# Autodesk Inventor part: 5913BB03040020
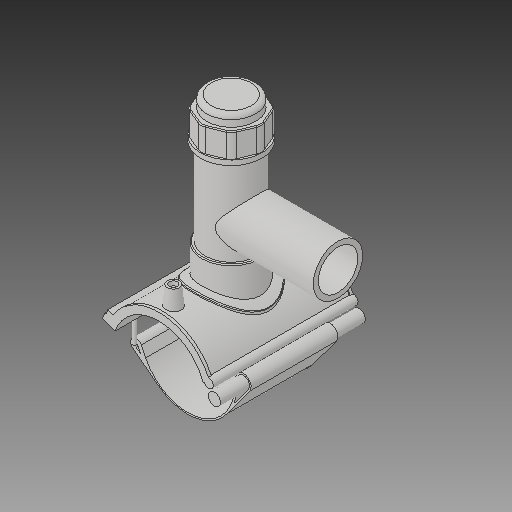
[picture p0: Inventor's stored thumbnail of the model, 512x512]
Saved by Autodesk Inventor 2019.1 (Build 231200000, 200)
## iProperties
Created: 2017-07
Part Number: 5913BB03040020
Material: Generic
Description: PLASSON HIGH VOLUME TAPPING TEE 4''IPSx 2''IPS
Document SubType Name: Modeling
Designer: KIM
Mass: 1712.7 g
Surface Area: 2671.49 cm^2
Volume: 1712.7 cm^3
Density: 1 g/cm^3
Appearance: Default
Author: KIM
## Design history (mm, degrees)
derived "5913B.ipt"
feature "Solid1::5913B.ipt"
feature "Solid2::5913B.ipt"
feature "Solid4::5913B.ipt"
feature "Solid5::5913B.ipt"
tag "TaggingFeature1"
body "Solid1"
body "Solid2"
other parameters: "d0" = 114.1, "d2" = 233.934, "d3" = 28.525, "d4" = 176.022, "d5" = 0, "d6" = 0.1, "d8" = 0, "d40" = 67.63848, "d41" = 91.28, "d43" = 0, "d45" = 0, "d47" = 170.6502, "d78" = 87.05, "d79" = 15, "d80" = 70.4088, "d82" = 5 deg, "d84" = 4, "d85" = 14, "d86" = 0, "d87" = 3, "d88" = 0, "d96" = 132.67548, "d97" = 3.52044, "d98" = 0, "d102" = 1.141, "d120" = 140 deg, "d121" = 24.228, "d122" = 20 deg, "d123" = 325.185, "d124" = 78.0444, "d126" = 0, "d153" = 176.022, "d154" = 0, "d159" = 3.1948, "d162" = 105.6132, "d163" = 0, "d164" = 57.05, "d169" = 4.0905, "d170" = 4.7922, "d172" = 0, "d173" = 1, "d175" = 57.05, "d176" = 20 deg, "d177" = 7.987, "d178" = 15.974, "d180" = 0, "d183" = 6.3896, "d184" = 6.3896, "d187" = 65.037, "d188" = 4.7922, "d189" = 7.987, "d190" = 0, "d191" = 97.5555, "d193" = 4.1076, "d194" = 2.0538, "d195" = 90 deg, "d197" = 0, "d199" = 0, "d200" = 7.987, "d202" = 0, "d203" = 194.818, "d204" = 71.10712, "d205" = 52.39472, "d206" = 63.62216, "d207" = 146.1135, "d208" = 151.95804, "d209" = 181.18074, "d210" = 64.37066, "d211" = 74.8496, "d212" = 59.87968, "d213" = 40.392, "d216" = 0, "d217" = 11.41, "d218" = 5.705, "d219" = 1.141, "d222" = 114.1, "d224" = 0, "d230" = 1.141, "d257" = 131.98, "d258" = 129.794, "d259" = 48.08, "d260" = 60.1, "d263" = 155.956, "d265" = 0, "d267" = 13.00006, "d268" = 2.60001, "d269" = 2.60001, "d271" = 2.60001, "d273" = 0, "d274" = 23.56194, "d275" = 91.28, "d277" = 45.64, "d278" = 182.56, "d280" = 0, "d281" = 114.1, "d283" = 0, "d285" = 0, "d290" = 11.41, "d291" = 14.833, "d293" = 62.755, "d294" = 58.7615, "d296" = 17.115, "d297" = 13.692, "d_" = 114.1, "B_" = 155.956, "L_" = 176.022, "d_t" = 6, "H_2" = 194.818, "H_1" = 74.93, "d_1" = 60.1, "H_" = 129.794, "d1" = 130.074, "d192" = 4.1076
